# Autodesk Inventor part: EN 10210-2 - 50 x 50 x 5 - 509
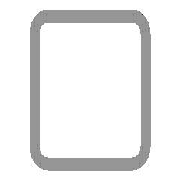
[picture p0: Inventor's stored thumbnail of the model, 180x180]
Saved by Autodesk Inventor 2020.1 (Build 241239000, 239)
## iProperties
Created: 2019-01
Part Number: EN 10210-2 - 50 x 50 x 5 - 509
Material: Stahl, weich
Description: Rohrleitung
Document SubType Name: Modeling
Standard: DIN
Designer: lutzd
Standard Revision: 2006-07
Standards Organization: DIN
Language: de-DE
Size Designation: 50 x 50 x 5
Categories: <MemberInstance><Categories><Category DisplayName="Profile" InternalName="089c4875-fa83-4c05-b084-43b9cc11f5ed" Mnemonic="GRDR"><CategoryParameter DisplayName="
Stock Number: 50 x 50 x 5
Mass: 3488.9 g
Surface Area: 1740.63 cm^2
Volume: 444.446 cm^3
Density: 7.85 g/cm^3
Appearance: Halbpoliert
IsCustomPart: 1
G_W: 50,000 mm
G_H: 50,000 mm
Dimensions: 50x50x509 mm
Mass: 3,489 kg
DocNumber: ADSK-014220
Folder: .
+F9523CC6-42A5-4DF1-B93A-EB821F9972A1+SCHNITTDETAIL1: Schnittwinkel 90,00 grd
G_L: 509,000 mm
_CCFamilyMember: 16
_CCFamilyDisplayName: DIN EN 10210-2 (USAS B17.1 quadratisch) - Rohrleitung — In Klammern angegebene Größen wurden aufgehoben
_FrameMemberDoc: Frame Member File
_Version: 15.0.0
_GetPNFromCC: 1
Title: Profil-Bauteil
Author: lutzd
Revision Number: -
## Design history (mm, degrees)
node "Startebene"
node "Endebene"
sketch "Skizze"
  geometry: L1 (-25, -17.5)-(-25, 17.5); L2 (-17.5, 25)-(17.5, 25); L3 (25, 17.5)-(25, -17.5); L4 (17.5, -25)-(-17.5, -25); L5 (-15, 20)-(15, 20); L6 (20, 15)-(20, -15); L7 (15, -20)-(-15, -20); L8 (-20, -15)-(-20, 15); L9 (0, 37.175)-(0, -37.175) reference; L10 (-37.175, 0)-(37.175, 0) reference; A1 r 7.5 centre (-17.5, -17.5) between (-25, -17.5) and (-17.5, -25); A2 r 7.5 centre (-17.5, 17.5) between (-17.5, 25) and (-25, 17.5); A3 r 7.5 centre (17.5, 17.5) between (25, 17.5) and (17.5, 25); A4 r 7.5 centre (17.5, -17.5) between (17.5, -25) and (25, -17.5); A5 r 5 centre (-15, -15) between (-20, -15) and (-15, -20); A6 r 5 centre (-15, 15) between (-15, 20) and (-20, 15); A7 r 5 centre (15, 15) between (20, 15) and (15, 20); A8 r 5 centre (15, -15) between (15, -20) and (20, -15)
  constraints: 16 end point, 16 point on circle, 16 tangent, 8 centre point, 6 equal radius, 4 parallel, 2 perpendicular, 2 other
  dimensions: "d7" = 7.5 radius of A1 (= G_IR); "d10" = 50 distance between parallel lines of L2 L4 (= G_H); "d11" = 50 distance between parallel lines of L1 L3 (= G_W); "d12" = 5 distance between parallel lines of L3 L6 (= G_T); "d15" = 25 distance between parallel lines of L2 L10 (= 0.5 x d10); "d16" = 25 distance between parallel lines of L9 L3 (= 0.5 x d11); "d19" = 5 radius of A5 (= G_T); "d20" = 5 distance between parallel lines of L4 L7 (= G_T)
extrude "Körper" new body sketch "Skizze" stored distance "d3" = 509 (= G_L); taper "d4" = 0 deg
node "Driven Length"
  sketch "Sketch3"
    geometry: L1 (0, 0)-(10, 0) reference
    constraints: 2 end point, 1 horizontal
  workplane "Work Plane3"
  sketch "Sketch4"
    geometry: L1 (-2, 50)-(12, 50) reference; L2 (-2, 559)-(12, 559) reference
    dimensions: "d18" = 509 distance between parallel lines of L1 L2 (derived)
workplane "Arbeitsebene4"
feature "Trennen1"
body "Solid1"
other parameters: "G_W" = 50 [user parameter; used in 1 equation term], "G_H" = 50 [user parameter; used in 1 equation term], "G_T" = 5 [user parameter; used in 3 equation terms], "G_IR" = 7.5 [user parameter; used in 1 equation term], "G_L" = 509 (= d18) [user parameter; used in 1 equation term], "G_OFFSET_END" = 0 [user parameter; used in 1 equation term], "d14" = 559 (= G_OFFSET_END + B_L), "B_L" = 559 [user parameter; used in 1 equation term], "d17" = 90 deg
